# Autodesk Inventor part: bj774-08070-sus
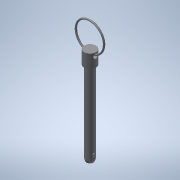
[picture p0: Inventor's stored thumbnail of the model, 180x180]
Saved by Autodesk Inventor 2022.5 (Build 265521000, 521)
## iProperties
Created: 2016-12
Part Number: bj774-08070-sus
Material: 一般
Document SubType Name: Modeling
Designer: imaocorp
Density: 1 g/cm^3
Appearance: 既定
Author: imaocorp
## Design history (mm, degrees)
node "bj774-08070-sus.x_t1"
node "bj774-08070-sus"
node "Base1"
